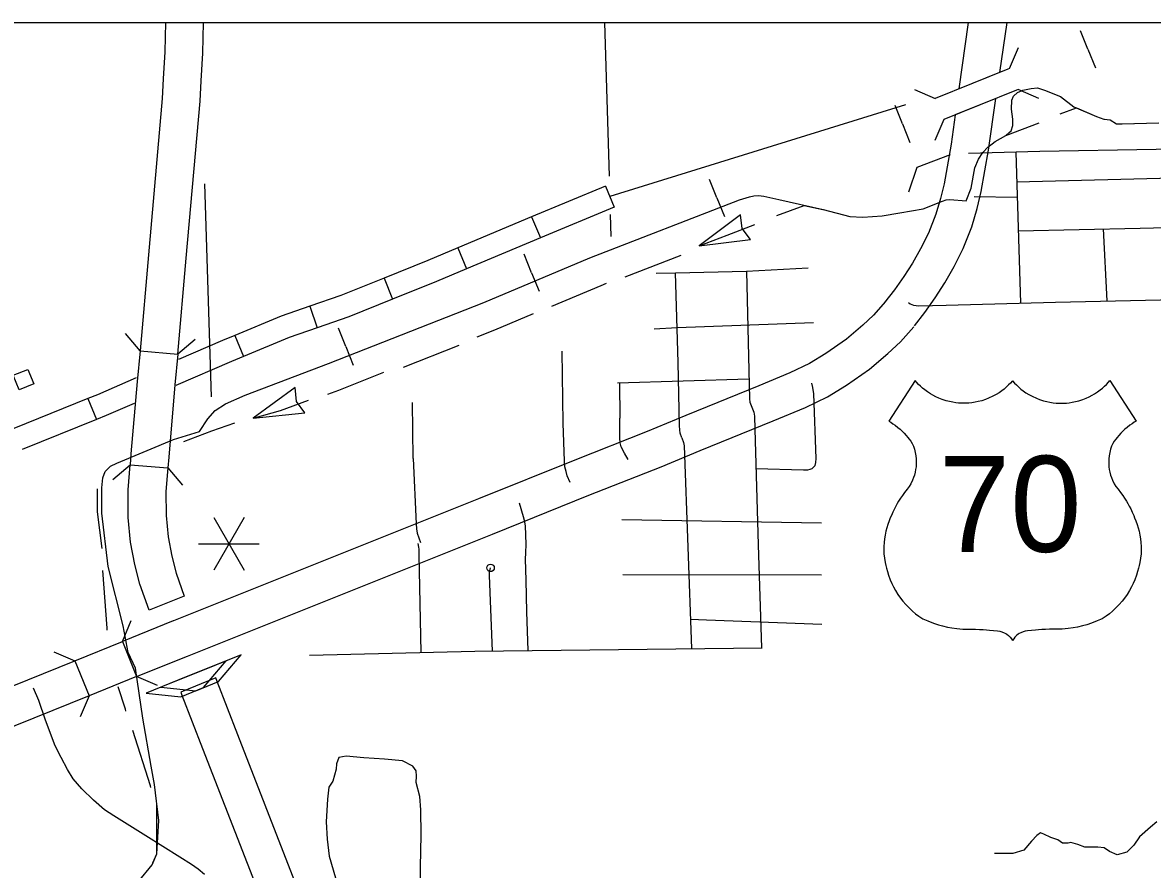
# Model space of a CAD drawing. Extents: x 155 to 3386, y 68 to 2138.
# Drawn here: x 1365.4 to 1578.6, y 1149.2 to 1309 of the extents above; entities that cross this region are included whole.
import ezdxf

# ---------------------------------------------------------------- set-up
doc = ezdxf.new("R2010")
doc.units = 0
for name, color, linetype in [('Default', 7, 'Continuous'), ('E_No Plot', 7, 'Continuous'), ('Level 10', 7, 'Continuous'), ('Level 15', 7, 'Continuous'), ('Level 22', 7, 'Continuous'), ('Level 32', 7, 'Continuous'), ('Level 33', 7, 'Continuous'), ('Level 34', 7, 'Continuous'), ('Level 35', 7, 'Continuous'), ('Level 37', 7, 'Continuous'), ('Level 40', 7, 'Continuous'), ('Level 42', 7, 'Continuous'), ('Level 43', 7, 'Continuous'), ('Level 48', 7, 'Continuous'), ('Level 5', 7, 'Continuous'), ('Level 56', 7, 'Continuous'), ('Level 6', 7, 'Continuous')]:
    doc.layers.add(name, color=color, linetype=linetype)

msp = doc.modelspace()

# ---------------------------------------------------------------- linework, layer by layer
at = {"layer": 'Default'}
msp.add_lwpolyline([(1150.5, 1308.99), (2342.15, 1308.99), (2342.15, 348.58), (1150.5, 348.58)], close=True, dxfattribs=at)
at = {"layer": 'E_No Plot'}
msp.add_lwpolyline([(1150.5, 1308.99), (2342.15, 1308.99), (2342.15, 348.58), (1150.5, 348.58)], close=True, dxfattribs=at)
msp.add_lwpolyline([(1150.5, 1308.99), (2342.15, 1308.99), (2342.15, 348.58), (1150.5, 348.58)], close=True, dxfattribs=at)
at = {"layer": 'Level 10'}
for p, q in [((1387.54, 1247.07), (1394.65, 1246.43)), ((1385.67, 1225.57), (1392.79, 1224.99))]:
    msp.add_line(p, q, dxfattribs=at)
for points in [[(1392.35, 1308.99), (1392.24, 1303.49), (1391.94, 1298.41), (1391.74, 1294.65), (1389.16, 1265.17), (1387.54, 1247.07)], [(1394.65, 1246.43), (1396.27, 1264.54), (1398.87, 1294.15), (1399.08, 1298.01), (1399.38, 1303.21), (1399.5, 1308.99)], [(1387.54, 1247.07), (1387.02, 1241.26), (1385.84, 1227.64), (1385.67, 1225.57)], [(1394.65, 1246.43), (1394.14, 1240.64), (1392.95, 1227.02), (1392.79, 1224.99)], [(1389.27, 1198.13), (1387.51, 1203.07), (1386.57, 1206.77), (1385.76, 1210.96), (1385.3, 1215.66), (1385.28, 1220.84), (1385.67, 1225.57)], [(1392.79, 1224.99), (1392.43, 1220.56), (1392.45, 1216.02), (1392.83, 1211.98), (1393.54, 1208.34), (1394.35, 1205.15), (1395.9, 1200.8), (1389.27, 1198.13)], [(1433.54, 1072.43), (1431.24, 1088.64), (1429.61, 1099.61), (1428.42, 1108.02), (1427.31, 1113.71), (1426.57, 1117.42), (1425.62, 1121.17), (1424.38, 1126.02), (1422.98, 1130.47), (1421.6, 1134.32), (1419.74, 1139.15), (1417.81, 1144.18), (1416.33, 1148.1), (1405.99, 1174.65), (1402.12, 1184.7), (1401.86, 1185.39), (1395.24, 1182.71)], [(1395.24, 1182.71), (1395.46, 1182.12), (1399.33, 1172.07), (1409.66, 1145.55), (1411.13, 1141.65), (1413.07, 1136.59), (1414.91, 1131.83), (1416.21, 1128.19), (1417.51, 1124.07), (1418.7, 1119.41), (1419.6, 1115.85), (1420.3, 1112.33), (1421.37, 1106.83), (1422.54, 1098.59), (1424.18, 1087.61), (1426.47, 1071.43)]]:
    msp.add_lwpolyline(points, dxfattribs=at)
at = {"layer": 'Level 15'}
for p, q in [((1528.06, 1256.16), (1528.22, 1256.35)), ((1384.23, 1192.24), (1386.9, 1185.62)), ((1375.25, 1188.62), (1377.92, 1181.99))]:
    msp.add_line(p, q, dxfattribs=at)
for points in [[(1551.12, 1308.99), (1549.77, 1299.59), (1542.1, 1296.49), (1543.9, 1308.99)], [(1533.72, 1251.8), (1535.64, 1254.3), (1537.61, 1257.06), (1539.44, 1259.87), (1541.18, 1262.96), (1542.86, 1266.38), (1544.5, 1270.48), (1545.54, 1273.94), (1546.3, 1277.15), (1547.65, 1284.91), (1549.06, 1294.68), (1541.4, 1291.58)], [(1541.4, 1291.58), (1540.6, 1286.04), (1539.3, 1278.59), (1538.64, 1275.79), (1537.75, 1272.84), (1536.33, 1269.29), (1534.85, 1266.29), (1533.33, 1263.58), (1531.71, 1261.09), (1529.9, 1258.55), (1528.06, 1256.16)], [(1528.22, 1256.35), (1525.94, 1253.78), (1523.93, 1251.91), (1520.86, 1249.27), (1516.98, 1246.59), (1513.86, 1244.7), (1510.18, 1242.93), (1504.33, 1240.48), (1490.53, 1234.87), (1483.22, 1231.83), (1469.59, 1226.47), (1451.41, 1219.13), (1393.83, 1196.12)], [(1396.48, 1189.49), (1454.07, 1212.51), (1472.23, 1219.84), (1485.9, 1225.2), (1493.25, 1228.27), (1507.05, 1233.87), (1513.11, 1236.41), (1517.27, 1238.41), (1520.87, 1240.59), (1525.24, 1243.61), (1528.69, 1246.58), (1531.06, 1248.79), (1533.56, 1251.61)], [(1393.81, 1196.11), (1384.23, 1192.24)], [(1375.25, 1188.62), (1384.23, 1192.24)], [(1310.27, 1162.39), (1333.46, 1171.74), (1375.25, 1188.62)], [(1386.9, 1185.62), (1396.49, 1189.49)], [(1386.9, 1185.62), (1377.92, 1181.99)], [(1377.92, 1181.99), (1336.14, 1165.12), (1312.94, 1155.76)]]:
    msp.add_lwpolyline(points, dxfattribs=at)
at = {"layer": 'Level 22'}
for points in [[(1552.2, 1241.43), (1551.82, 1241), (1551.46, 1240.63), (1551.05, 1240.25), (1550.61, 1239.87), (1550.19, 1239.54), (1549.67, 1239.18), (1549.12, 1238.84), (1548.49, 1238.49), (1547.69, 1238.12), (1547.07, 1237.88), (1546.38, 1237.66), (1545.74, 1237.49), (1545.16, 1237.37), (1544.54, 1237.28), (1543.97, 1237.22), (1543.2, 1237.18), (1542.56, 1237.19), (1542.01, 1237.22), (1541.49, 1237.28), (1540.96, 1237.36), (1540.29, 1237.49), (1539.68, 1237.65), (1538.92, 1237.9), (1538.29, 1238.15), (1537.71, 1238.41), (1537.18, 1238.69), (1536.69, 1238.98), (1536.14, 1239.34), (1535.64, 1239.71), (1535.21, 1240.06), (1534.85, 1240.38), (1534.47, 1240.74), (1534.11, 1241.13), (1533.81, 1241.47), (1528.87, 1233.82), (1529.22, 1233.61), (1529.64, 1233.33), (1530.04, 1233.05), (1530.57, 1232.64), (1531, 1232.27), (1531.37, 1231.92), (1531.75, 1231.53), (1532.15, 1231.09), (1532.43, 1230.75), (1532.71, 1230.4), (1532.99, 1230), (1533.26, 1229.59), (1533.51, 1229.1), (1533.71, 1228.51), (1533.85, 1227.92), (1533.96, 1227.28), (1534.02, 1226.7), (1534.04, 1226.13), (1534.03, 1225.6), (1533.99, 1225.18), (1533.92, 1224.66), (1533.82, 1224.17), (1533.69, 1223.64), (1533.54, 1223.17), (1533.33, 1222.65), (1533.01, 1221.98), (1532.68, 1221.45), (1532.29, 1220.97), (1531.8, 1220.35), (1531.41, 1219.8), (1531.04, 1219.26), (1530.71, 1218.72), (1530.42, 1218.24), (1530.17, 1217.79), (1529.9, 1217.26), (1529.6, 1216.64), (1529.33, 1216.03), (1529.14, 1215.57), (1528.92, 1214.99), (1528.68, 1214.28), (1528.49, 1213.69), (1528.31, 1213.04), (1528.15, 1212.29), (1528.04, 1211.62), (1527.96, 1210.92), (1527.91, 1210.16), (1527.91, 1209.45), (1527.94, 1208.75), (1528.03, 1207.93), (1528.15, 1207.15), (1528.28, 1206.56), (1528.42, 1206.05), (1528.58, 1205.46), (1528.81, 1204.74), (1529.14, 1203.86), (1529.42, 1203.21), (1529.75, 1202.54), (1530.1, 1201.89), (1530.57, 1201.13), (1531.05, 1200.44), (1531.52, 1199.84), (1532.05, 1199.23), (1532.73, 1198.52), (1533.31, 1197.98), (1533.91, 1197.48)], [(1552.2, 1241.43), (1552.57, 1241), (1552.93, 1240.63), (1553.34, 1240.25), (1553.78, 1239.87), (1554.21, 1239.54), (1554.72, 1239.18), (1555.28, 1238.84), (1555.91, 1238.49), (1556.71, 1238.12), (1557.32, 1237.88), (1558.02, 1237.66), (1558.65, 1237.49), (1559.24, 1237.37), (1559.85, 1237.28), (1560.42, 1237.22), (1561.2, 1237.18), (1561.83, 1237.19), (1562.38, 1237.22), (1562.9, 1237.28), (1563.43, 1237.36), (1564.1, 1237.49), (1564.72, 1237.65), (1565.47, 1237.9), (1566.11, 1238.15), (1566.68, 1238.41), (1567.22, 1238.69), (1567.7, 1238.98), (1568.25, 1239.34), (1568.75, 1239.71), (1569.18, 1240.06), (1569.55, 1240.38), (1569.92, 1240.74), (1570.29, 1241.13), (1570.58, 1241.47), (1575.53, 1233.82), (1575.17, 1233.61), (1574.75, 1233.33), (1574.35, 1233.05), (1573.82, 1232.64), (1573.4, 1232.27), (1573.02, 1231.92), (1572.64, 1231.53), (1572.25, 1231.09), (1571.97, 1230.75), (1571.69, 1230.4), (1571.41, 1230), (1571.13, 1229.59), (1570.88, 1229.1), (1570.69, 1228.51), (1570.54, 1227.92), (1570.43, 1227.28), (1570.37, 1226.7), (1570.35, 1226.13), (1570.37, 1225.6), (1570.4, 1225.18), (1570.47, 1224.66), (1570.57, 1224.17), (1570.71, 1223.64), (1570.86, 1223.17), (1571.06, 1222.65), (1571.38, 1221.98), (1571.71, 1221.45), (1572.11, 1220.97), (1572.59, 1220.35), (1572.99, 1219.8), (1573.35, 1219.26), (1573.69, 1218.72), (1573.97, 1218.24), (1574.22, 1217.79), (1574.5, 1217.26), (1574.8, 1216.64), (1575.07, 1216.03), (1575.25, 1215.57), (1575.47, 1214.99), (1575.71, 1214.28), (1575.9, 1213.69), (1576.08, 1213.04), (1576.25, 1212.29), (1576.36, 1211.62), (1576.44, 1210.92), (1576.48, 1210.16), (1576.49, 1209.45), (1576.45, 1208.75), (1576.37, 1207.93), (1576.24, 1207.15), (1576.11, 1206.56), (1575.98, 1206.05), (1575.81, 1205.46), (1575.58, 1204.74), (1575.26, 1203.86), (1574.97, 1203.21), (1574.65, 1202.54), (1574.29, 1201.89), (1573.82, 1201.13), (1573.34, 1200.44), (1572.88, 1199.84), (1572.35, 1199.23), (1571.66, 1198.52), (1571.08, 1197.98), (1570.49, 1197.48)], [(1533.91, 1197.48), (1534.53, 1197.01), (1535.27, 1196.53), (1536.21, 1196.11), (1537.3, 1195.69), (1538.2, 1195.4), (1539, 1195.17), (1539.91, 1194.96), (1540.76, 1194.81), (1541.68, 1194.68), (1542.84, 1194.58), (1543.72, 1194.55), (1544.48, 1194.55), (1545.22, 1194.55), (1545.95, 1194.52), (1546.65, 1194.49), (1547.26, 1194.45), (1547.86, 1194.4), (1548.63, 1194.32), (1549.38, 1194.22), (1549.83, 1194.16), (1550.2, 1194.09), (1550.65, 1193.9), (1550.91, 1193.76), (1551.14, 1193.61), (1551.44, 1193.36), (1551.74, 1193.06), (1551.98, 1192.75), (1552.2, 1192.4)], [(1570.49, 1197.48), (1569.87, 1197.01), (1569.12, 1196.53), (1568.19, 1196.11), (1567.09, 1195.69), (1566.2, 1195.4), (1565.39, 1195.17), (1564.48, 1194.96), (1563.63, 1194.81), (1562.71, 1194.68), (1561.56, 1194.58), (1560.67, 1194.55), (1559.91, 1194.55), (1559.18, 1194.55), (1558.44, 1194.52), (1557.74, 1194.49), (1557.13, 1194.45), (1556.53, 1194.4), (1555.77, 1194.32), (1555.01, 1194.22), (1554.56, 1194.16), (1554.19, 1194.09), (1553.74, 1193.9), (1553.48, 1193.76), (1553.26, 1193.61), (1552.95, 1193.36), (1552.66, 1193.06), (1552.42, 1192.75), (1552.2, 1192.4)]]:
    msp.add_lwpolyline(points, dxfattribs=at)
at = {"layer": 'Level 32'}
for p, q in [((1475.36, 1278.16), (1477.01, 1274.2)), ((1461.44, 1272.33), (1463.1, 1268.38)), ((1447.53, 1266.5), (1449.18, 1262.55)), ((1433.59, 1260.8), (1435.19, 1256.83)), ((1419.59, 1255.49), (1420.99, 1251.44)), ((1405.42, 1249.99), (1407.06, 1246.03)), ((1377.71, 1238.08), (1379.32, 1234.11))]:
    msp.add_line(p, q, dxfattribs=at)
for points in [[(1475.36, 1278.16), (1461.44, 1272.33)], [(1477.01, 1274.2), (1463.1, 1268.38)], [(1461.44, 1272.33), (1447.53, 1266.5)], [(1463.1, 1268.38), (1449.18, 1262.55)], [(1447.53, 1266.5), (1441.89, 1264.14), (1433.59, 1260.8)], [(1449.18, 1262.55), (1443.52, 1260.18), (1435.19, 1256.83)], [(1433.59, 1260.8), (1425.44, 1257.52), (1419.59, 1255.49)], [(1435.19, 1256.83), (1426.95, 1253.51), (1420.99, 1251.44)], [(1419.59, 1255.49), (1414.15, 1253.6), (1405.42, 1249.99)], [(1405.42, 1249.99), (1403.11, 1249.03), (1394.79, 1245.43)], [(1420.99, 1251.44), (1415.67, 1249.59), (1407.06, 1246.03)], [(1407.06, 1246.03), (1404.78, 1245.08), (1394.31, 1240.55)], [(1386.81, 1241.97), (1379.5, 1238.8), (1377.71, 1238.08)], [(1377.71, 1238.08), (1363.72, 1232.44)], [(1386.42, 1237.13), (1381.16, 1234.85), (1379.32, 1234.11)], [(1379.32, 1234.11), (1365.33, 1228.47)]]:
    msp.add_lwpolyline(points, dxfattribs=at)
at = {"layer": 'Level 33'}
for points in [[(1651.44, 1287.45), (1638.55, 1286.9), (1629.38, 1286.55), (1605.37, 1285.55), (1579.28, 1285.06), (1557.33, 1284.68), (1543.92, 1284.32)], [(1552.81, 1284.56), (1553.69, 1256.07)], [(1552.98, 1278.94), (1584.89, 1279.76), (1598.53, 1279.76)], [(1553.07, 1276), (1544.99, 1276.15)], [(1553.27, 1269.69), (1576.27, 1270.22), (1611.73, 1271.12)], [(1569.3, 1270.06), (1570.03, 1256.48)], [(1484.93, 1261.72), (1488.61, 1261.8), (1501.99, 1262.12), (1513.66, 1262.72)], [(1489.78, 1230.69), (1489.5, 1231.55), (1489.39, 1232.19), (1489.36, 1232.92), (1489.07, 1244.84), (1488.61, 1261.8)], [(1501.99, 1262.12), (1502.54, 1238.03), (1502.61, 1237.39), (1502.85, 1236.75), (1503.16, 1236.15)], [(1532.57, 1256.16), (1532.88, 1255.91), (1533.49, 1255.7), (1534.49, 1255.54), (1539.7, 1255.66), (1560.3, 1256.27), (1602.77, 1257.2), (1629.1, 1257.97)], [(1514.63, 1252.35), (1488.89, 1251.38), (1484.58, 1251.18)], [(1468.69, 1222.26), (1468.16, 1223.49), (1467.97, 1224.29), (1467.72, 1225.16), (1467.66, 1226.28), (1467.41, 1233.43), (1467.23, 1247)], [(1477.65, 1241.06), (1502.46, 1241.78)], [(1478.05, 1241.07), (1478.09, 1234.34)], [(1503.77, 1224.88), (1512.74, 1224.64), (1513.55, 1224.64), (1514.01, 1224.74), (1514.38, 1224.86), (1514.73, 1225.17), (1514.94, 1225.45), (1515.11, 1226.03), (1515.13, 1226.78), (1514.7, 1238.94), (1514.54, 1240.15), (1514.34, 1240.96)], [(1503.16, 1236.15), (1503.41, 1235.5), (1503.52, 1234.73), (1503.55, 1232.29), (1504.21, 1210.48), (1504.84, 1191.06)], [(1489.78, 1230.69), (1490.11, 1229.8), (1490.24, 1229.18), (1491.6, 1190.89)], [(1439.09, 1226.79), (1439.64, 1214.43), (1439.71, 1213.49), (1439.83, 1212.69), (1440.14, 1211.82), (1440.48, 1210.92)], [(1516.14, 1214.58), (1478.44, 1215.2)], [(1439.95, 1210.71), (1440.12, 1210.04), (1440.17, 1209.66), (1440.17, 1208.66), (1440.55, 1190.15)], [(1454.07, 1190.43), (1453.5, 1204.66), (1453.5, 1205.33), (1453.69, 1206.13)], [(1478.68, 1204.88), (1516.14, 1204.82)], [(1491.41, 1196.43), (1494.46, 1196.31), (1516.2, 1195.5)], [(1419.51, 1189.66), (1450.71, 1190.39), (1504.96, 1191.06)], [(1399.73, 1148.3), (1398.53, 1149.29), (1397.26, 1150.14), (1395.04, 1151.55), (1388.66, 1155.6), (1382.59, 1159.34), (1380.87, 1160.51), (1378.74, 1162.32), (1376.57, 1164.47), (1374.93, 1166.35), (1373.85, 1168.1), (1372.65, 1170.38), (1371.54, 1172.55), (1369.72, 1177.37), (1368.45, 1181.08), (1367.42, 1183.42)]]:
    msp.add_lwpolyline(points, dxfattribs=at)
msp.add_circle((1453.69, 1206.13), 0.714, dxfattribs=at)
at = {"layer": 'Level 34'}
for points in [[(1532, 1293.45), (1476.19, 1276.18)], [(1439.09, 1226.79), (1438.94, 1237.32)], [(1479.65, 1226.59), (1478.96, 1227.77), (1478.34, 1228.95), (1478.16, 1229.7), (1478.09, 1230.69), (1478.09, 1234.34)], [(1459.1, 1218.39), (1459.87, 1215.85), (1460.07, 1215.14), (1460.21, 1214.04), (1460.35, 1210.61), (1460.26, 1208.99), (1460.21, 1207.75), (1460.35, 1203.8), (1460.45, 1197.85), (1460.73, 1190.51)]]:
    msp.add_lwpolyline(points, dxfattribs=at)
at = {"layer": 'Level 35'}
for points in [[(1440.33, 1163.01), (1439.67, 1165.65), (1439.73, 1166.84), (1439.67, 1167.86), (1439.01, 1168.7), (1437.1, 1169.72), (1433.69, 1170.07), (1429.8, 1170.31), (1426.45, 1170.61), (1425.08, 1170.37), (1424.6, 1169.18), (1424.54, 1168.16), (1423.94, 1165.89), (1423.17, 1164.75), (1422.93, 1162.48), (1422.69, 1158.23), (1422.87, 1154.94), (1423.23, 1151.71), (1424.9, 1146.14)], [(1440.39, 1143.69), (1440.45, 1149.67), (1440.57, 1155.77), (1440.51, 1160.5), (1440.33, 1163.01)], [(1579.46, 1158.2), (1578.25, 1157.23), (1576.18, 1155.4), (1575.09, 1153.83), (1573.75, 1152.49), (1571.93, 1152), (1570.48, 1152.61), (1569.51, 1153.34), (1568.29, 1153.46), (1567.93, 1153.46), (1566.71, 1153.46), (1565.86, 1153.46), (1564.53, 1153.95), (1563.19, 1154.31), (1562.71, 1154.19), (1561.61, 1154.19), (1560.76, 1154.8), (1559.43, 1155.28), (1558.09, 1155.89), (1557.49, 1156.13), (1556.76, 1155.65), (1555.79, 1154.55), (1554.33, 1152.85), (1552.27, 1152.25), (1550.32, 1152.25), (1548.82, 1152.25)]]:
    msp.add_lwpolyline(points, dxfattribs=at)
at = {"layer": 'Level 37'}
for points in [[(1551.65, 1300.35), (1553.34, 1304.29)], [(1551.65, 1300.35), (1551.34, 1300.23), (1537.63, 1294.68)], [(1553.25, 1296.37), (1552.94, 1296.25), (1539.24, 1290.7)], [(1557.19, 1294.69), (1553.25, 1296.37)], [(1533.69, 1296.35), (1537.63, 1294.68)], [(1539.24, 1290.7), (1537.57, 1286.76)], [(1387.54, 1247.07), (1384.79, 1250.35)], [(1397.94, 1249.18), (1394.65, 1246.43)], [(1382.4, 1222.79), (1385.67, 1225.57)], [(1392.79, 1224.99), (1395.56, 1221.72)], [(1384.23, 1192.24), (1385.9, 1196.19)], [(1371.3, 1190.29), (1375.25, 1188.62)], [(1390.85, 1183.94), (1386.9, 1185.62)], [(1377.92, 1181.99), (1376.25, 1178.05)]]:
    msp.add_lwpolyline(points, dxfattribs=at)
at = {"layer": 'Level 40'}
for p, q in [((1566.43, 1303.96), (1565.02, 1307.47)), ((1566.43, 1303.96), (1567.83, 1300.46)), ((1531.44, 1289.87), (1530.04, 1293.38)), ((1531.44, 1289.87), (1532.84, 1286.37)), ((1496.41, 1275.92), (1495, 1279.41)), ((1496.41, 1275.92), (1497.82, 1272.42)), ((1461.43, 1261.8), (1460.02, 1265.3)), ((1461.43, 1261.8), (1462.85, 1258.3)), ((1426.39, 1247.87), (1424.98, 1251.37)), ((1426.39, 1247.87), (1427.79, 1244.37))]:
    msp.add_line(p, q, dxfattribs=at)
at = {"layer": 'Level 42'}
for p, q in [((1403.81, 1188.58), (1396.26, 1185.55)), ((1406.61, 1189.71), (1399.05, 1186.67)), ((1399.55, 1183.55), (1403.81, 1188.58)), ((1402.35, 1184.67), (1406.61, 1189.71)), ((1396.26, 1185.55), (1388.7, 1182.51)), ((1399.05, 1186.67), (1391.49, 1183.63)), ((1391.49, 1183.63), (1398.06, 1182.94)), ((1395.26, 1181.82), (1399.55, 1183.55)), ((1398.06, 1182.94), (1402.35, 1184.67)), ((1388.7, 1182.51), (1395.26, 1181.82))]:
    msp.add_line(p, q, dxfattribs=at)
at = {"layer": 'Level 43'}
for p, q in [((1500.88, 1272.75), (1493.04, 1266.85)), ((1501.2, 1270.16), (1500.88, 1272.75)), ((1502.78, 1268.05), (1501.21, 1270.13)), ((1493.04, 1266.85), (1502.78, 1268.05)), ((1416.81, 1240.14), (1408.87, 1234.39)), ((1417.08, 1237.54), (1416.81, 1240.14)), ((1418.62, 1235.4), (1417.09, 1237.51)), ((1408.87, 1234.39), (1418.62, 1235.4))]:
    msp.add_line(p, q, dxfattribs=at)
for points in [[(1387.26, 1146.95), (1389.81, 1150.13), (1390.71, 1152.17), (1391.11, 1158.45), (1390.25, 1165.29), (1389.66, 1168.69), (1388.06, 1177.79), (1386.72, 1187.19), (1385.3, 1190.15), (1384.39, 1195.17), (1381.56, 1206.4), (1380.32, 1216.46), (1380.32, 1221.21), (1380.55, 1223.11), (1380.99, 1224.28), (1382, 1225.33), (1383.16, 1225.9), (1393.89, 1230.34), (1398.78, 1231.88), (1400.35, 1234.27), (1401.75, 1235.84), (1403.65, 1237.08), (1407.36, 1238.73), (1423.12, 1244.67), (1452.4, 1256.22), (1472.45, 1264.64), (1500.66, 1275.54), (1502.54, 1276.1), (1503.39, 1276.32), (1504.29, 1276.38), (1505.25, 1276.27), (1508.13, 1275.59), (1516.49, 1273.72), (1521.52, 1272.42), (1523.95, 1272.31), (1527.57, 1272.54), (1530.95, 1273.1), (1535.36, 1273.89), (1538.97, 1275.31), (1539.65, 1275.53), (1540.39, 1275.59), (1543.44, 1275.36), (1544.4, 1277.79), (1545.07, 1281.58), (1545.81, 1283.22), (1546.6, 1284.46), (1547.56, 1285.48), (1548.92, 1286.55), (1550.95, 1287.68), (1551.57, 1288.25), (1551.97, 1288.59), (1552.25, 1289.55), (1552.25, 1290.79), (1552.02, 1292.66), (1552.08, 1294.35), (1552.36, 1295.09), (1553.15, 1295.82), (1554.17, 1296.27), (1555.69, 1296.55), (1556.94, 1296.67), (1558.24, 1296.27), (1561.23, 1295.03), (1563.77, 1293.11), (1568.06, 1291.3), (1569.42, 1290.79), (1570.61, 1290.62), (1571.85, 1289.89), (1572.92, 1289.89), (1579.81, 1290.11)], [(1561.19, 1291.81), (1564.29, 1292.89), (1568.06, 1291.3), (1569.42, 1290.79), (1569.54, 1290.77)], [(1550.91, 1287.66), (1550.95, 1287.68), (1557.21, 1290.09)], [(1569.54, 1290.77), (1570.61, 1290.62), (1571.85, 1289.89), (1572.92, 1289.89), (1574.98, 1289.95)], [(1532.64, 1277.09), (1534.18, 1281.7), (1534.21, 1281.72), (1540.47, 1284.12)], [(1507.75, 1272.61), (1512.91, 1274.52), (1516.43, 1273.74)], [(1520.08, 1272.8), (1521.52, 1272.42), (1523.95, 1272.31), (1527.57, 1272.54), (1530.95, 1273.1), (1531.28, 1273.16)], [(1498.32, 1268.89), (1503.6, 1270.93)], [(1493.04, 1266.85), (1498.32, 1268.89)], [(1479.12, 1261.04), (1489.67, 1265.12)], [(1465.26, 1255.52), (1474.55, 1259.42), (1475.55, 1259.81)], [(1451.19, 1249.74), (1454.51, 1251.05), (1461.77, 1254.09)], [(1437.24, 1243.99), (1447.77, 1248.14)], [(1422.96, 1238.87), (1425.05, 1239.66), (1433.57, 1243.02)], [(1408.87, 1234.39), (1414.04, 1235.79), (1419.34, 1237.79)], [(1395.8, 1229.97), (1401.09, 1231.97), (1405.41, 1233.52)], [(1380.37, 1209.78), (1379.51, 1216.73), (1379.51, 1221.04)], [(1381.36, 1194.37), (1381.36, 1194.74), (1380.5, 1205.65)], [(1384.88, 1179.1), (1384.79, 1179.46), (1383.44, 1183.69)], [(1389.6, 1164.67), (1389.51, 1165.04), (1386.18, 1175.46)], [(1389.96, 1150.46), (1390.71, 1152.17), (1390.72, 1161.58)]]:
    msp.add_lwpolyline(points, dxfattribs=at)
at = {"layer": 'Level 48'}
for p, q in [((1407.17, 1215.62), (1401.46, 1205.72)), ((1401.46, 1215.62), (1407.17, 1205.72)), ((1398.6, 1210.67), (1410.03, 1210.67))]:
    msp.add_line(p, q, dxfattribs=at)
at = {"layer": 'Level 5'}
msp.add_lwpolyline([(1399.7, 1278.59), (1400.95, 1238.4)], dxfattribs=at)
at = {"layer": 'Level 56'}
msp.add_lwpolyline([(1366.37, 1243.58), (1367.48, 1240.83), (1364.72, 1239.71), (1363.6, 1242.47)], close=True, dxfattribs=at)
at = {"layer": 'Level 6'}
for points in [[(1475.2, 1308.99), (1476.07, 1280.03)], [(1476.29, 1272.82), (1476.41, 1268.63)]]:
    msp.add_lwpolyline(points, dxfattribs=at)

# ---------------------------------------------------------------- texts
at = {"layer": 'Level 22'}
msp.add_text('70', height=18.103, dxfattribs=at).set_placement((1538.3, 1209.15))

doc.saveas('drawing.dxf')
